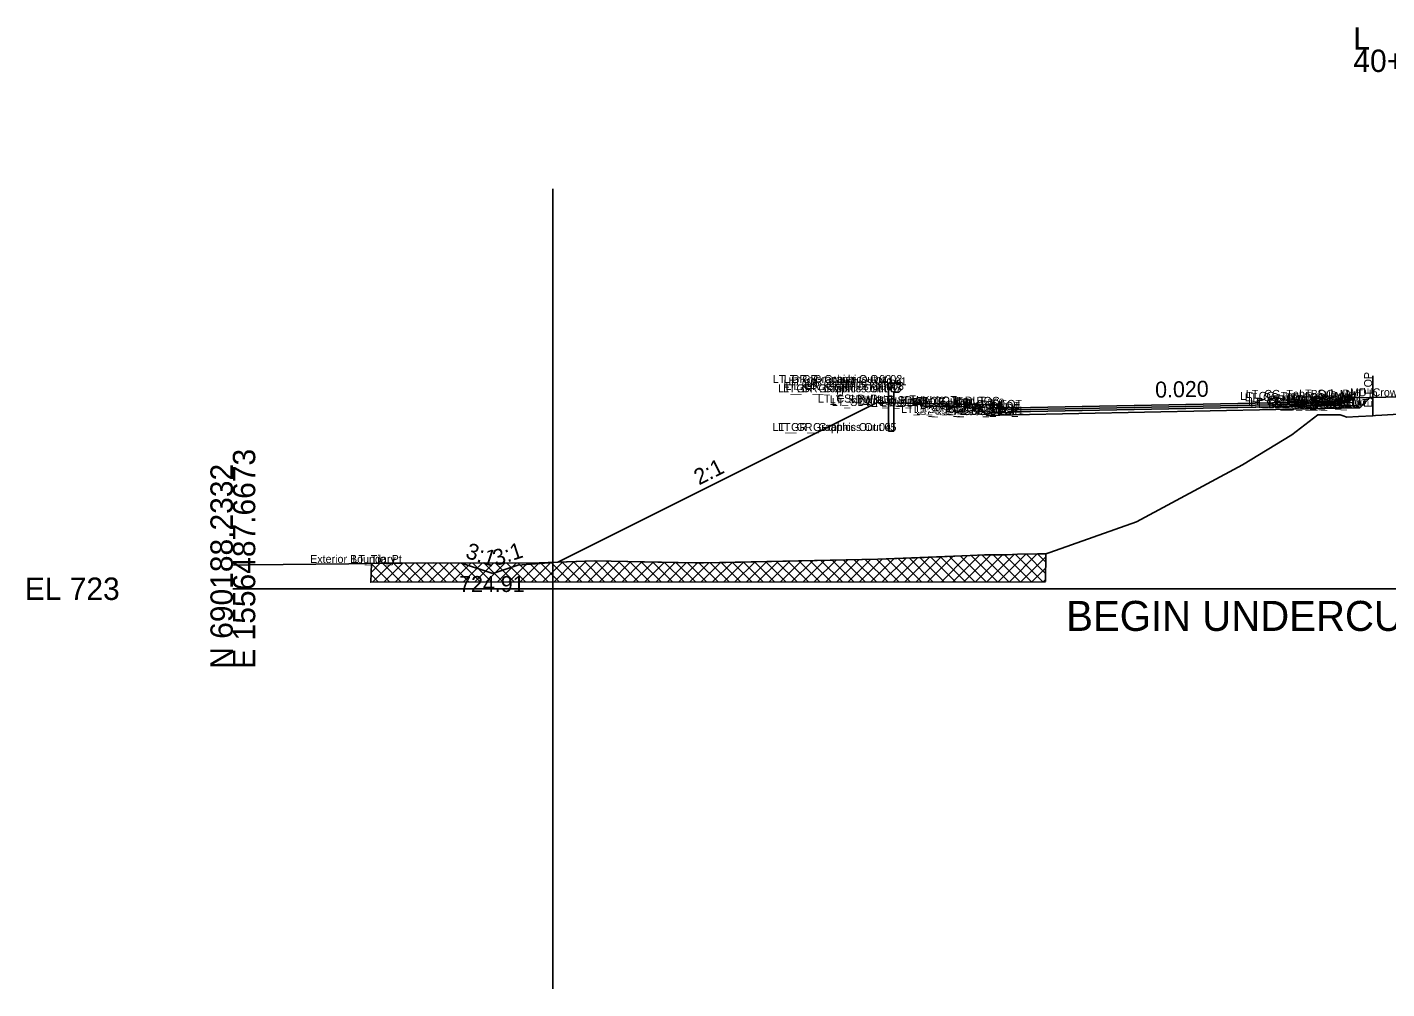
# Model space of a CAD drawing. Extents: x -26 to 6300, y -50 to 9577.
# Drawn here: x -25.7 to 144.2, y 6450 to 6570.2 of the extents above; entities that cross this region are included whole.
import ezdxf

# ---------------------------------------------------------------- set-up
doc = ezdxf.new("R2010")
doc.units = 0
for name, color, linetype in [('Default', 7, 'Continuous'), ('Exist Cross Section Cell', 7, 'Continuous'), ('Exist XS Ground Line', 7, 'Continuous'), ('Prop CMT Conc Surface', 7, 'Continuous'), ('Prop CMT Concrete Structures', 7, 'Continuous'), ('Prop CMT Guardrail Graphics', 7, 'Continuous'), ('Prop CMT Pvmt Course 1', 7, 'Continuous'), ('Prop CMT Pvmt Course 1 CG', 7, 'Continuous'), ('Prop CMT Pvmt Course 2', 7, 'Continuous'), ('Prop CMT Pvmt Course 3', 7, 'Continuous'), ('Prop CMT Pvmt Surface', 7, 'Continuous'), ('Prop CMT Slope Grass', 7, 'Continuous'), ('Prop CMT Subgrade Earthwork', 7, 'Continuous'), ('Prop XS DDE', 7, 'Continuous'), ('Prop XS DDE Text', 7, 'Continuous'), ('Prop XS Earthwork Shape', 7, 'Continuous'), ('Prop XS Label Text', 7, 'Continuous'), ('Prop XS SE Text', 7, 'Continuous'), ('Prop XS Side Slope Text', 7, 'Continuous'), ('Prop XS Undercut Exc', 7, 'Continuous'), ('Prop XS Undercut Exc Hatch', 7, 'Continuous'), ('Prop XSC Text', 7, 'Continuous'), ('Scratch_Level_7', 7, 'Continuous')]:
    doc.layers.add(name, color=color, linetype=linetype)

msp = doc.modelspace()

# ---------------------------------------------------------------- linework, layer by layer
at = {"layer": 'Exist Cross Section Cell'}
msp.add_line((0, 6500), (150, 6500), dxfattribs=at)
at = {"layer": 'Exist XS Ground Line'}
msp.add_lwpolyline([(0, 6502.94), (2.15, 6502.97), (14.48, 6503.13), (21.06, 6503.23), (37.12, 6503.19), (45.16, 6503.49), (57.75, 6503.22), (58.42, 6503.23), (58.81, 6503.22), (80.6, 6503.7), (92.13, 6504.15), (93.92, 6504.24), (96.73, 6504.24), (98.03, 6504.32), (100.53, 6504.36), (101.56, 6504.36), (102.06, 6504.54), (112.9, 6508.35), (126.16, 6515.5), (132.33, 6519.23), (135.58, 6521.72), (138.34, 6521.72), (138.74, 6521.59), (139.17, 6521.45), (140.65, 6521.54), (142.44, 6521.62), (142.77, 6521.66), (143.57, 6521.71), (149.23, 6522.02)], dxfattribs=at)
at = {"layer": 'Prop CMT Conc Surface'}
for points in [[(91, 6523.07), (86, 6523.17)], [(138.5, 6523.42), (139.25, 6523.44), (139.25, 6523.6), (140.01, 6523.85)], [(95.5, 6522.48), (95.5, 6522.98), (95, 6522.98)], [(97.5, 6522.6), (95.5, 6522.48)]]:
    msp.add_lwpolyline(points, dxfattribs=at)
at = {"layer": 'Prop CMT Concrete Structures'}
for points in [[(86, 6522.84), (86, 6523.17)], [(86, 6523.17), (91, 6523.07)], [(91, 6523.07), (91, 6522.74)], [(138.5, 6523.42), (139.25, 6523.44), (139.25, 6523.6), (140.01, 6523.85)], [(138.5, 6522.84), (138.5, 6523.42)], [(140.01, 6523.85), (140.01, 6522.87)], [(91, 6522.74), (86, 6522.84)], [(97.5, 6522.6), (95.5, 6522.48), (95.5, 6522.98), (95, 6522.98)], [(95, 6522.98), (95, 6521.97), (97.5, 6522.02)], [(97.5, 6522.02), (97.5, 6522.6)], [(140.01, 6522.87), (138.5, 6522.84)]]:
    msp.add_lwpolyline(points, dxfattribs=at)
at = {"layer": 'Prop CMT Guardrail Graphics'}
for points in [[(81.9, 6519.71), (81.9, 6525.71)], [(81.9, 6525.71), (83.23, 6525.71), (83.51, 6525.42)], [(83.51, 6524.84), (83.23, 6524.55), (82.57, 6524.55)], [(83.51, 6525.42), (83.23, 6525.13)], [(83.23, 6525.13), (83.51, 6524.84)], [(82.57, 6524.55), (82.57, 6519.71)], [(82.57, 6519.71), (81.9, 6519.71)]]:
    msp.add_lwpolyline(points, dxfattribs=at)
at = {"layer": 'Prop CMT Pvmt Course 1'}
for points in [[(138.5, 6523.42), (97.5, 6522.6)], [(97.5, 6522.35), (138.5, 6523.17)], [(138.5, 6523.17), (138.5, 6523.42)], [(138.5, 6523.17), (138.5, 6523.17), (138.5, 6523.17)], [(97.5, 6522.6), (97.5, 6522.35)]]:
    msp.add_lwpolyline(points, dxfattribs=at)
at = {"layer": 'Prop CMT Pvmt Course 1 CG'}
for points in [[(97.5, 6522.02), (94.5, 6521.96), (94.2, 6521.66)], [(94.2, 6521.66), (97.5, 6521.73)], [(97.5, 6521.77), (97.5, 6522.02)], [(138.5, 6522.84), (140.51, 6522.88), (140.8, 6522.59)], [(138.5, 6522.59), (138.5, 6522.84)], [(140.76, 6522.59), (138.5, 6522.55)]]:
    msp.add_lwpolyline(points, dxfattribs=at)
at = {"layer": 'Prop CMT Pvmt Course 2'}
for points in [[(138.5, 6523.17), (97.5, 6522.35)], [(138.5, 6522.92), (138.5, 6523.17)], [(97.5, 6522.1), (138.5, 6522.92)], [(97.5, 6522.35), (97.5, 6522.1)]]:
    msp.add_lwpolyline(points, dxfattribs=at)
at = {"layer": 'Prop CMT Pvmt Course 3'}
for points in [[(138.5, 6522.92), (97.5, 6522.1)], [(97.5, 6521.73), (138.5, 6522.55)], [(97.5, 6522.1), (97.5, 6521.73)], [(138.5, 6522.55), (138.5, 6522.92)]]:
    msp.add_lwpolyline(points, dxfattribs=at)
at = {"layer": 'Prop CMT Pvmt Surface'}
msp.add_lwpolyline([(138.5, 6523.42), (97.5, 6522.6)], dxfattribs=at)
at = {"layer": 'Prop CMT Slope Grass'}
msp.add_line((80.5, 6523.27), (40.59, 6503.32), dxfattribs=at)
for points in [[(95, 6522.98), (80.5, 6523.27)], [(140.01, 6523.85), (150, 6524.05)]]:
    msp.add_lwpolyline(points, dxfattribs=at)
at = {"layer": 'Prop CMT Subgrade Earthwork'}
msp.add_line((94.2, 6521.66), (92.84, 6523.02), dxfattribs=at)
for points in [[(142.1, 6523.89), (140.8, 6522.59)], [(97.5, 6521.73), (94.2, 6521.66)], [(138.5, 6522.55), (97.5, 6521.73)], [(140.8, 6522.59), (138.5, 6522.55)], [(138.5, 6522.55), (138.5, 6522.55)]]:
    msp.add_lwpolyline(points, dxfattribs=at)
at = {"layer": 'Prop XS DDE'}
for p, q in [((35.61, 6502.95), (32.48, 6501.91)), ((40.59, 6503.32), (35.61, 6502.95))]:
    msp.add_line(p, q, dxfattribs=at)
msp.add_lwpolyline([(32.48, 6501.91), (28.58, 6503.21)], dxfattribs=at)
at = {"layer": 'Prop XS Earthwork Shape'}
msp.add_lwpolyline([(150, 6524.05), (142.1, 6523.89), (140.8, 6522.59), (138.5, 6522.55), (97.5, 6521.73), (94.2, 6521.66), (92.83, 6523.03), (91, 6523.07), (91, 6522.74), (86, 6522.84), (86, 6523.17), (80.5, 6523.27), (40.59, 6503.32), (45.16, 6503.49), (57.75, 6503.22), (58.42, 6503.23), (58.81, 6503.22), (80.6, 6503.7), (92.13, 6504.15), (93.92, 6504.24), (96.73, 6504.24), (98.03, 6504.32), (100.53, 6504.36), (101.56, 6504.36), (102.06, 6504.54), (112.9, 6508.35), (126.16, 6515.5), (132.33, 6519.23), (135.58, 6521.72), (138.34, 6521.72), (138.74, 6521.59), (139.17, 6521.45), (140.65, 6521.54), (142.44, 6521.62), (142.77, 6521.66), (143.57, 6521.71), (149.23, 6522.02)], dxfattribs=at)
at = {"layer": 'Prop XS Label Text'}
msp.add_line((142.44, 6526.62), (142.44, 6521.62), dxfattribs=at)
at = {"layer": 'Prop XS Undercut Exc'}
for p, q in [((100.53, 6504.36), (98.03, 6504.32)), ((101.56, 6504.36), (100.53, 6504.36)), ((101.55, 6500.89), (101.56, 6504.36)), ((25.95, 6500.83), (28.34, 6503.21)), ((84.11, 6503.83), (84.11, 6503.83)), ((86.36, 6503.92), (84.12, 6503.83)), ((92.13, 6504.15), (86.36, 6503.92)), ((93.92, 6504.24), (92.13, 6504.15)), ((95.32, 6504.24), (93.92, 6504.24)), ((96.73, 6504.24), (95.32, 6504.24)), ((98.03, 6504.32), (96.73, 6504.24)), ((101.27, 6500.89), (101.55, 6501.17))]:
    msp.add_line(p, q, dxfattribs=at)
for points in [[(25.03, 6503.22), (17.32, 6503.17), (17.23, 6500.82), (101.55, 6500.87)], [(40.59, 6503.32), (37.12, 6503.19), (25.03, 6503.22)], [(55.01, 6503.28), (45.34, 6503.49), (40.59, 6503.32)], [(84.12, 6503.83), (80.6, 6503.7), (61.6, 6503.28), (58.81, 6503.22), (58.42, 6503.23), (57.75, 6503.22), (55.01, 6503.28)]]:
    msp.add_lwpolyline(points, dxfattribs=at)
at = {"layer": 'Prop XS Undercut Exc Hatch'}
for p, q in [((95.6, 6500.88), (99.06, 6504.34)), ((97.02, 6500.88), (100.5, 6504.36)), ((99.14, 6504.34), (101.55, 6501.92)), ((100.53, 6504.36), (101.56, 6503.33)), ((17.28, 6502.05), (18.4, 6503.18)), ((17.32, 6503.13), (19.63, 6500.82)), ((17.46, 6500.82), (19.83, 6503.19)), ((18.69, 6503.18), (21.04, 6500.82)), ((18.88, 6500.82), (21.25, 6503.2)), ((20.09, 6503.19), (22.46, 6500.82)), ((20.29, 6500.82), (22.67, 6503.2)), ((21.5, 6503.2), (23.87, 6500.83)), ((21.71, 6500.82), (24.1, 6503.21)), ((22.9, 6503.21), (25.28, 6500.83)), ((23.12, 6500.82), (25.52, 6503.22)), ((24.31, 6503.21), (26.7, 6500.83)), ((24.54, 6500.83), (26.93, 6503.21)), ((25.72, 6503.22), (28.11, 6500.83)), ((27.14, 6503.21), (29.52, 6500.83)), ((27.37, 6500.83), (29.75, 6503.21)), ((28.56, 6503.21), (30.94, 6500.83)), ((28.78, 6500.83), (31.16, 6503.2)), ((29.97, 6503.21), (32.35, 6500.83)), ((30.2, 6500.83), (32.57, 6503.2)), ((31.39, 6503.2), (33.76, 6500.83)), ((31.61, 6500.83), (33.98, 6503.2)), ((32.81, 6503.2), (35.18, 6500.83)), ((33.03, 6500.83), (35.39, 6503.19)), ((34.23, 6503.19), (36.59, 6500.83)), ((34.44, 6500.83), (36.8, 6503.19)), ((35.65, 6503.19), (38, 6500.83)), ((35.86, 6500.83), (38.26, 6503.23)), ((37.06, 6503.19), (39.42, 6500.83)), ((37.27, 6500.83), (39.73, 6503.29)), ((38.43, 6503.24), (40.83, 6500.84)), ((38.69, 6500.83), (41.19, 6503.34)), ((39.79, 6503.29), (42.24, 6500.84)), ((40.1, 6500.84), (42.66, 6503.39)), ((41.16, 6503.34), (43.66, 6500.84)), ((41.52, 6500.84), (44.13, 6503.44)), ((42.52, 6503.39), (45.07, 6500.84)), ((42.93, 6500.84), (45.58, 6503.48)), ((43.89, 6503.44), (46.48, 6500.84)), ((44.35, 6500.84), (46.96, 6503.45)), ((45.25, 6503.48), (47.9, 6500.84)), ((45.76, 6500.84), (48.35, 6503.42)), ((46.69, 6503.46), (49.31, 6500.84)), ((47.18, 6500.84), (49.73, 6503.39)), ((48.14, 6503.43), (50.72, 6500.84)), ((48.59, 6500.84), (51.12, 6503.36)), ((49.58, 6503.4), (52.14, 6500.84)), ((50.01, 6500.84), (52.5, 6503.33)), ((51.03, 6503.36), (53.55, 6500.84)), ((51.42, 6500.84), (53.89, 6503.3)), ((52.47, 6503.33), (54.96, 6500.84)), ((52.84, 6500.84), (55.27, 6503.27)), ((53.92, 6503.3), (56.38, 6500.85)), ((54.25, 6500.84), (56.65, 6503.24)), ((55.36, 6503.27), (57.79, 6500.85)), ((55.67, 6500.84), (58.05, 6503.22)), ((56.81, 6503.24), (59.2, 6500.85)), ((57.08, 6500.85), (59.47, 6503.24)), ((58.24, 6503.22), (60.62, 6500.85)), ((58.5, 6500.85), (60.92, 6503.27)), ((59.64, 6503.24), (62.03, 6500.85)), ((59.91, 6500.85), (62.37, 6503.3)), ((61.02, 6503.27), (63.44, 6500.85)), ((61.33, 6500.85), (63.81, 6503.33)), ((62.41, 6503.3), (64.86, 6500.85)), ((62.74, 6500.85), (65.26, 6503.36)), ((63.79, 6503.33), (66.27, 6500.85)), ((64.16, 6500.85), (66.7, 6503.39)), ((65.18, 6503.36), (67.68, 6500.85)), ((65.57, 6500.85), (68.15, 6503.42)), ((66.56, 6503.39), (69.1, 6500.85)), ((66.99, 6500.85), (69.59, 6503.46)), ((67.94, 6503.42), (70.51, 6500.85)), ((68.41, 6500.85), (71.04, 6503.49)), ((69.33, 6503.45), (71.92, 6500.85)), ((69.82, 6500.85), (72.49, 6503.52)), ((70.71, 6503.48), (73.34, 6500.86)), ((71.24, 6500.85), (73.93, 6503.55)), ((72.1, 6503.51), (74.75, 6500.86)), ((72.65, 6500.86), (75.38, 6503.58)), ((73.48, 6503.54), (76.16, 6500.86)), ((74.07, 6500.86), (76.82, 6503.61)), ((74.86, 6503.57), (77.58, 6500.86)), ((75.48, 6500.86), (78.27, 6503.65)), ((76.25, 6503.6), (78.99, 6500.86)), ((76.9, 6500.86), (79.71, 6503.68)), ((77.63, 6503.63), (80.4, 6500.86)), ((78.31, 6500.86), (81.17, 6503.72)), ((79.02, 6503.66), (81.82, 6500.86)), ((79.73, 6500.86), (82.64, 6503.78)), ((80.4, 6503.69), (83.23, 6500.86)), ((81.14, 6500.86), (84.11, 6503.83)), ((81.76, 6503.74), (84.64, 6500.86)), ((82.56, 6500.86), (85.59, 6503.89)), ((83.12, 6503.8), (86.06, 6500.86)), ((83.97, 6500.86), (87.06, 6503.95)), ((84.49, 6503.85), (87.47, 6500.86)), ((85.39, 6500.86), (88.53, 6504.01)), ((85.85, 6503.9), (88.88, 6500.87)), ((86.8, 6500.86), (90, 6504.07)), ((87.21, 6503.96), (90.3, 6500.87)), ((88.41, 6504), (91.54, 6500.87)), ((88.52, 6500.86), (91.79, 6504.14)), ((89.53, 6504.05), (92.71, 6500.87)), ((89.94, 6500.87), (93.28, 6504.21)), ((90.89, 6504.1), (94.12, 6500.87)), ((91.35, 6500.87), (94.72, 6504.24)), ((92.25, 6504.15), (95.53, 6500.88)), ((92.77, 6500.87), (96.11, 6504.21)), ((93.59, 6504.22), (96.94, 6500.88)), ((94.19, 6500.87), (97.56, 6504.25)), ((94.99, 6504.24), (98.35, 6500.88)), ((96.43, 6504.22), (99.76, 6500.89)), ((97.8, 6504.26), (101.17, 6500.89)), ((98.44, 6500.88), (101.56, 6504)), ((17.27, 6501.77), (18.22, 6500.82)), ((99.86, 6500.89), (101.55, 6502.58))]:
    msp.add_line(p, q, dxfattribs=at)
at = {"layer": 'Scratch_Level_7'}
msp.add_line((40, 6550), (40, 6450), dxfattribs=at)

# ---------------------------------------------------------------- texts
at = {"layer": 'Default'}
for s, height, p in [('LT_GR_Graphics Out 03', 1, (67.47, 6525.71)), ('LT_GR_Graphics Out 02', 1, (68.84, 6525.71)), ('LT_GR_Graphics Out 01', 1, (69.4, 6525.42)), ('LT_GR_Graphics Out 06', 1, (68.11, 6524.55)), ('LT_GR_Graphics Out 07', 1, (68.75, 6524.55)), ('LT_GR_Graphics Out 09', 1, (68.78, 6525.13)), ('LT_GR_Graphics Out 08', 1, (69.05, 6524.84)), ('LT_CG_Top_BOC_Med', 1, (126.57, 6523.85)), ('LT_Sub_DLT_In', 1, (133.22, 6523.89)), ('MD_Crown Point', 1, (139.58, 6524.05)), ('LT_CSLP_Pnt', 1, (73.1, 6523.27)), ('LT_SDWK_Out_Top', 1, (74.58, 6523.17)), ('LT_SDWK_Out_Bot', 1, (74.83, 6522.84)), ('LT_Sub_Trench_Out_DLT', 1, (78.22, 6523.02)), ('LT_SDWK_In_Top', 1, (80.74, 6523.07)), ('LT_SDWK_In_Bot', 1, (80.99, 6522.74)), ('LT_CG_Top_BOC', 1, (84.81, 6522.98)), ('LT_CG_Top_Face', 1, (85.34, 6522.98)), ('LT_CG_Top_Gut', 1, (85.87, 6522.48)), ('LT_PV2_OEOT', 1, (88.99, 6522.35)), ('LT_PV3_OEOT', 1, (88.99, 6522.1)), ('LT_PV1_OEOT', 1, (89.23, 6522.6)), ('LT_CG_Bot_IE', 1, (89.34, 6522.02)), ('LT_CG_Top_Face_Med', 1, (125.87, 6523.6)), ('LT_CG_Top_Gut_Med', 1, (126.42, 6523.44)), ('LT_CG_Bot_BOC_Med', 1, (126.85, 6522.87)), ('LT_CG_Bot_IE_Med', 1, (127.09, 6522.84)), ('LT_Sub_IEOT_CG_1', 1, (127.13, 6522.59)), ('LT_PV2_OEEOP', 1, (129.29, 6523.17)), ('LT_PV3_OEEOP', 1, (129.29, 6522.92)), ('LT_Sub_OEEOP', 1, (129.33, 6522.55)), ('LT_PV2_IEEOP', 1, (130.05, 6523.17)), ('LT_Sub_IEEOP', 1, (130.09, 6522.55)), ('LT_CG1_Shelf_In', 1, (130.71, 6522.88)), ('LT_PV2_PGL', 1, (131.26, 6523.17)), ('LT_Sub_PGL', 1, (131.31, 6522.55)), ('LT_PV1_PGL', 1, (131.5, 6523.42)), ('LT_Sub_IEOP', 1, (133.05, 6522.63)), ('LT_CG1_Shelf_Out', 1, (83.48, 6521.96)), ('LT_CG_Bot_BOC', 1, (85.09, 6521.97)), ('LT_Sub_OEOT_CG_1', 1, (85.36, 6521.77)), ('LT_Sub_OEOP', 1, (85.77, 6521.7)), ('LT_Sub_OEOT', 1, (89.04, 6521.73)), ('LT_GR_Graphics Out 04', 1, (67.44, 6519.71)), ('LT_GR_Graphics Out 05', 1, (68.12, 6519.71)), ('Exterior Boundary', 1, (9.66, 6503.22)), ('LT_Tie_Pt', 1, (14.94, 6503.22)), ('-', 0.0001, (0, 6500))]:
    msp.add_text(s, height=height, dxfattribs=at).set_placement(p)
at = {"layer": 'Exist Cross Section Cell'}
for s, p in [('L', (140, 6567.38)), ('40+00.00 / 1', (140, 6564.58)), ('EL 723', (-26, 6498.6))]:
    msp.add_text(s, height=2.8, dxfattribs=at).set_placement(p)
for s, p in [('E 1556487.6673', (2.8, 6490)), ('N 690188.2332', (0, 6490))]:
    msp.add_text(s, height=2.8, rotation=90, dxfattribs=at).set_placement(p)
at = {"layer": 'Prop XS DDE Text'}
for rotation, p in [(341.5651, (28.95, 6503.91)), (17.9773, (32.87, 6502.82))]:
    msp.add_text('3:1', height=2, rotation=rotation, dxfattribs=at).set_placement(p)
msp.add_text('724.91', height=2, dxfattribs=at).set_placement((28.27, 6499.59))
at = {"layer": 'Prop XS Label Text'}
msp.add_text('E. EOP', height=1, rotation=90, dxfattribs=at).set_placement((142.34, 6522.64))
at = {"layer": 'Prop XS SE Text'}
msp.add_text('0.020', height=2, rotation=1.1458, dxfattribs=at).set_placement((115.25, 6523.87))
at = {"layer": 'Prop XS Side Slope Text'}
msp.add_text('2:1', height=2, rotation=26.5651, dxfattribs=at).set_placement((58.24, 6512.9))
at = {"layer": 'Prop XSC Text'}
msp.add_text('BEGIN UNDERCUT AT STA 39+75', height=3.75, dxfattribs=at).set_placement((104.12, 6494.73))

doc.saveas('drawing.dxf')
